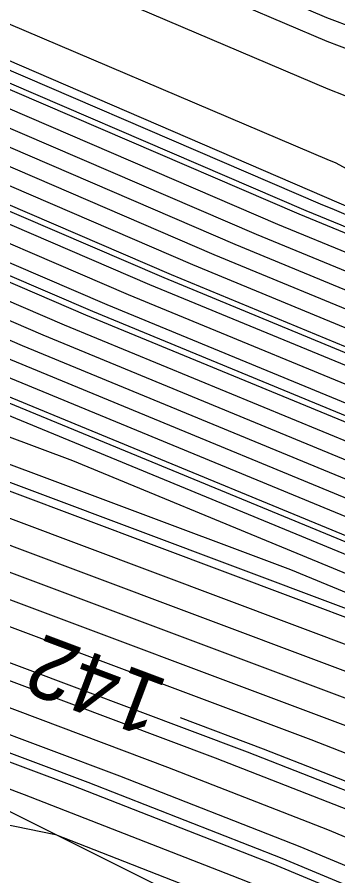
# Model space of a CAD drawing. Extents: x 2354170 to 2357230, y 866100 to 868290.
# Drawn here: x 2355142.84 to 2355153.3, y 867504.12 to 867532.18 of the extents above; entities that cross this region are included whole.
import ezdxf

# ---------------------------------------------------------------- set-up
doc = ezdxf.new("R2010")
doc.units = 0
for name, color, linetype in [('Default', 7, 'Continuous'), ('DTM Contours Major', 7, 'Continuous'), ('DTM Contours Minor', 7, 'Continuous'), ('PH Exist DTM Breakline', 7, 'Continuous')]:
    doc.layers.add(name, color=color, linetype=linetype)

msp = doc.modelspace()

# ---------------------------------------------------------------- linework, layer by layer
at = {"layer": 'Default'}
for points in [[(2355039.748, 867582.774), (2355057.845, 867572.501), (2355066.09, 867568.423), (2355075.66, 867563.616), (2355088.2, 867558.035), (2355090.288, 867556.998), (2355109.078, 867548.638), (2355117.687, 867544.873), (2355118.143, 867544.673), (2355135.4, 867537.032), (2355142.924, 867534.128), (2355152.971, 867529.837), (2355153.53, 867529.622), (2355160.154, 867526.024), (2355180.934, 867517.127), (2355182.414, 867516.349), (2355190.855, 867512.84), (2355199.936, 867509.264)], [(2355030.605, 867581.098), (2355048.031, 867569.375), (2355053.29, 867566.596), (2355066.627, 867561.622), (2355069.054, 867560.678), (2355086.4, 867553.004), (2355087.112, 867552.723), (2355112.383, 867541.543), (2355114.567, 867540.679), (2355114.963, 867540.522), (2355137.014, 867531.279), (2355139.122, 867530.678), (2355151.331, 867525.417), (2355153.823, 867524.387), (2355178.286, 867513.844), (2355180.51, 867512.86), (2355190.971, 867508.066), (2355192.601, 867507.384), (2355218.305, 867495.571)], [(2354995.047, 867580.65), (2355018.365, 867571.741), (2355022.674, 867569.867), (2355022.938, 867569.764), (2355041.304, 867560.814), (2355048.738, 867556.887), (2355052.264, 867555.571), (2355072.009, 867547.892), (2355078.691, 867544.936), (2355084.387, 867542.691), (2355094.899, 867538.04), (2355111.939, 867531.298), (2355115.029, 867530.075), (2355125.868, 867525.532), (2355139.851, 867521.546), (2355141.602, 867520.791), (2355158.318, 867513.884), (2355164.901, 867511.046), (2355180.153, 867504.304), (2355183.645, 867502.704), (2355196.955, 867497.127)], [(2355029.69, 867579.758), (2355040.479, 867572.499), (2355052.965, 867565.903), (2355065.601, 867561.19), (2355069.265, 867559.765), (2355085.849, 867552.427), (2355086.917, 867552.006), (2355111.135, 867541.292), (2355114.379, 867540.009), (2355114.968, 867539.776), (2355136.218, 867530.869), (2355139.174, 867530.026), (2355150.636, 867525.087), (2355154.144, 867523.637), (2355177.33, 867513.644), (2355180.485, 867512.249), (2355190.448, 867507.683), (2355192.912, 867506.651), (2355217.532, 867495.337)], [(2355043.958, 867577.984), (2355056.525, 867570.85), (2355067.342, 867565.501), (2355072.214, 867563.054), (2355087.851, 867556.095), (2355088.894, 867555.577), (2355112.103, 867545.25), (2355116.28, 867543.423), (2355116.501, 867543.327), (2355137.772, 867533.908), (2355140.329, 867532.921), (2355153.012, 867527.504), (2355153.21, 867527.428), (2355155.552, 867526.156), (2355180.709, 867515.384), (2355181.269, 867515.089), (2355191.411, 867510.874), (2355196.056, 867509.044)], [(2355028.633, 867577.026), (2355052.315, 867564.516), (2355063.549, 867560.326), (2355069.688, 867557.938), (2355084.748, 867551.275), (2355086.528, 867550.573), (2355108.637, 867540.792), (2355114.004, 867538.669), (2355114.977, 867538.283), (2355134.626, 867530.048), (2355139.278, 867528.721), (2355149.246, 867524.426), (2355154.786, 867522.137), (2355175.418, 867513.244), (2355180.434, 867511.027), (2355189.401, 867506.917), (2355193.534, 867505.186)], [(2355002.655, 867575.912), (2355019.366, 867569.527), (2355021.702, 867568.511), (2355022.012, 867568.39), (2355043.608, 867557.866), (2355048.087, 867555.5), (2355050.212, 867554.707), (2355072.431, 867546.066), (2355077.59, 867543.784), (2355083.997, 867541.258), (2355092.402, 867537.54), (2355111.563, 867529.958), (2355115.038, 867528.583), (2355124.276, 867524.711), (2355139.955, 867520.242), (2355140.213, 867520.131), (2355158.96, 867512.383), (2355162.989, 867510.647), (2355180.102, 867503.082), (2355182.598, 867501.938), (2355197.577, 867495.662)], [(2355029.785, 867575.552), (2355051.989, 867563.822), (2355062.523, 867559.893), (2355069.899, 867557.025), (2355084.197, 867550.699), (2355086.333, 867549.857), (2355107.388, 867540.542), (2355113.816, 867537.999), (2355114.982, 867537.537), (2355133.83, 867529.637), (2355139.331, 867528.069), (2355148.551, 867524.095), (2355155.107, 867521.386), (2355174.462, 867513.045), (2355180.408, 867510.416), (2355188.878, 867506.534), (2355193.845, 867504.453)], [(2355196.022, 867499.325), (2355185.215, 867503.853), (2355180.229, 867506.138), (2355167.77, 867511.646), (2355157.355, 867516.135), (2355143.687, 867521.783), (2355139.695, 867523.503), (2355128.257, 867526.764), (2355115.015, 867532.314), (2355112.502, 867533.308), (2355098.646, 867538.791), (2355084.971, 867544.841), (2355080.343, 867546.665), (2355071.376, 867550.632), (2355055.342, 867556.868), (2355049.713, 867558.967), (2355037.849, 867565.235), (2355024.326, 867571.825), (2355024.132, 867571.901), (2355016.865, 867575.061)], [(2355194.778, 867502.255), (2355187.308, 867505.385), (2355180.331, 867508.582), (2355171.594, 867512.445), (2355156.07, 867519.136), (2355146.466, 867523.104), (2355139.487, 867526.112), (2355131.441, 867528.406), (2355114.996, 867535.299), (2355113.253, 867535.988), (2355103.641, 867539.791), (2355085.749, 867547.707), (2355082.545, 867548.97), (2355070.532, 867554.285), (2355059.445, 867558.597), (2355051.014, 867561.741), (2355033.241, 867571.131), (2355026.177, 867574.573)], [(2354998.866, 867573.748), (2355010.208, 867572.11), (2355019.866, 867568.42), (2355021.216, 867567.833), (2355021.55, 867567.703), (2355044.76, 867556.392), (2355047.762, 867554.806), (2355049.186, 867554.275), (2355072.643, 867545.153), (2355077.039, 867543.207), (2355083.803, 867540.541), (2355091.153, 867537.289), (2355111.376, 867529.288), (2355115.043, 867527.837), (2355123.48, 867524.301), (2355138.516, 867520.014), (2355140.061, 867519.404), (2355144.636, 867517.685), (2355159.281, 867511.633), (2355162.033, 867510.447), (2355180.076, 867502.471), (2355182.075, 867501.555), (2355197.888, 867494.929)], [(2355195.089, 867501.523), (2355186.785, 867505.002), (2355180.306, 867507.971), (2355170.638, 867512.245), (2355156.392, 867518.385), (2355145.772, 867522.774), (2355139.539, 867525.46), (2355130.645, 867527.995), (2355115.001, 867534.553), (2355113.065, 867535.318), (2355102.393, 867539.541), (2355085.555, 867546.99), (2355081.995, 867548.394), (2355070.743, 867553.372), (2355058.419, 867558.165), (2355050.689, 867561.048), (2355034.393, 867569.657), (2355025.715, 867573.886)], [(2355048.169, 867573.195), (2355055.206, 867569.2), (2355068.594, 867562.579), (2355068.769, 867562.491), (2355086.8, 867554.466), (2355087.501, 867554.156), (2355087.501, 867554.156), (2355114.881, 867542.043), (2355114.942, 867542.019), (2355114.954, 867542.014), (2355138.607, 867532.1), (2355139.018, 867531.983), (2355152.72, 867526.078), (2355153.181, 867525.888), (2355180.198, 867514.243), (2355180.561, 867514.083), (2355190.76, 867509.409), (2355191.967, 867508.907), (2355192.176, 867508.825), (2355218.458, 867497.985)], [(2355017.865, 867572.848), (2355023.16, 867570.545), (2355023.401, 867570.451), (2355040.152, 867562.287), (2355049.063, 867557.58), (2355053.29, 867556.004), (2355071.798, 867548.806), (2355079.242, 867545.512), (2355084.581, 867543.407), (2355096.148, 867538.29), (2355112.126, 867531.968), (2355115.024, 867530.822), (2355126.665, 867525.943), (2355139.799, 867522.198), (2355142.297, 867521.122), (2355157.997, 867514.634), (2355165.857, 867511.246), (2355180.178, 867504.915), (2355184.168, 867503.087), (2355196.644, 867497.86)], [(2355195.711, 867500.057), (2355185.738, 867504.236), (2355180.255, 867506.749), (2355168.726, 867511.846), (2355157.034, 867516.885), (2355144.382, 867522.113), (2355139.643, 867524.155), (2355129.053, 867527.174), (2355115.01, 867533.06), (2355112.69, 867533.978), (2355099.895, 867539.041), (2355085.165, 867545.557), (2355080.893, 867547.241), (2355071.165, 867551.545), (2355056.368, 867557.3), (2355050.038, 867559.661), (2355036.697, 867566.709), (2355024.789, 867572.512), (2355024.618, 867572.579)], [(2355194.467, 867502.988), (2355187.831, 867505.768), (2355180.357, 867509.194), (2355172.55, 867512.645), (2355155.749, 867519.886), (2355147.161, 867523.435), (2355139.435, 867526.765), (2355132.238, 867528.816), (2355114.991, 867536.045), (2355113.441, 867536.658), (2355104.89, 867540.042), (2355085.944, 867548.423), (2355083.096, 867549.546), (2355070.321, 867555.198), (2355060.471, 867559.029), (2355051.339, 867562.435), (2355032.089, 867572.605)], [(2355001.207, 867570.699), (2355017.762, 867568.308), (2355020.366, 867567.313), (2355020.73, 867567.155), (2355021.087, 867567.016), (2355045.912, 867554.918), (2355047.437, 867554.112), (2355048.16, 867553.843), (2355072.854, 867544.239), (2355076.489, 867542.631), (2355083.608, 867539.825), (2355089.904, 867537.039), (2355111.188, 867528.618), (2355115.048, 867527.091), (2355122.684, 867523.89), (2355136.293, 867520.011), (2355140.195, 867518.469), (2355151.754, 867514.126), (2355159.602, 867510.883), (2355161.077, 867510.247), (2355180.05, 867501.86), (2355181.552, 867501.172), (2355198.199, 867494.196)], [(2355070.126, 867550.287), (2355071.587, 867549.719), (2355079.792, 867546.089), (2355084.776, 867544.124), (2355097.397, 867538.54), (2355112.314, 867532.638), (2355115.02, 867531.568), (2355127.461, 867526.353), (2355139.747, 867522.851), (2355142.992, 867521.452), (2355157.676, 867515.384), (2355162.877, 867513.143)], [(2355177.5, 867508.589), (2355169.682, 867512.045), (2355156.713, 867517.635), (2355145.077, 867522.443), (2355139.591, 867524.808), (2355129.849, 867527.585), (2355115.005, 867533.806), (2355112.877, 867534.648), (2355101.144, 867539.291), (2355085.36, 867546.274), (2355085.011, 867546.411)], [(2355074.048, 867546.171), (2355078.14, 867544.36), (2355084.192, 867541.974), (2355093.651, 867537.79), (2355111.751, 867530.628), (2355115.034, 867529.329), (2355125.072, 867525.122), (2355139.903, 867520.894), (2355140.907, 867520.461), (2355158.639, 867513.134), (2355163.945, 867510.847), (2355166.979, 867509.506)], [(2355099.408, 867545.678), (2355109.886, 867541.042), (2355114.192, 867539.339), (2355114.972, 867539.03), (2355135.422, 867530.458), (2355139.226, 867529.374), (2355149.941, 867524.756), (2355154.465, 867522.887), (2355176.374, 867513.444), (2355180.459, 867511.638), (2355189.925, 867507.3), (2355191.442, 867506.665)], [(2355095.736, 867544.894), (2355106.139, 867540.292), (2355113.628, 867537.328), (2355114.987, 867536.791), (2355133.034, 867529.227), (2355139.383, 867527.417), (2355147.856, 867523.765), (2355155.428, 867520.636), (2355173.506, 867512.845), (2355180.383, 867509.805), (2355187.942, 867506.34)], [(2355075.387, 867541.479), (2355083.219, 867538.391), (2355087.406, 867536.539), (2355110.812, 867527.278), (2355115.057, 867525.598), (2355121.092, 867523.069), (2355131.846, 867520.003), (2355140.464, 867516.599), (2355158.655, 867509.764), (2355159.218, 867509.544), (2355160.871, 867508.852), (2355169.056, 867505.475), (2355179.999, 867500.637), (2355180.505, 867500.406), (2355198.821, 867492.731)], [(2355199.132, 867491.999), (2355179.982, 867500.023), (2355179.974, 867500.026), (2355179.803, 867500.102), (2355161.933, 867507.475), (2355158.324, 867508.984), (2355157.096, 867509.466), (2355140.598, 867515.664), (2355129.622, 867520), (2355120.295, 867522.659), (2355115.062, 867524.852), (2355110.625, 867526.608), (2355086.157, 867536.289), (2355083.024, 867537.675), (2355074.837, 867540.902)], [(2355075.489, 867539.058), (2355082.635, 867536.242), (2355083.66, 867535.788), (2355110.249, 867525.268), (2355115.071, 867523.36), (2355118.703, 867521.838), (2355125.176, 867519.992), (2355140.867, 867513.794), (2355153.977, 867508.868), (2355156.537, 867507.865), (2355164.057, 867504.72), (2355179.317, 867498.424), (2355181.309, 867497.592), (2355194.726, 867492.64)], [(2355085.248, 867538.296), (2355088.655, 867536.789), (2355111, 867527.948), (2355115.053, 867526.344), (2355121.888, 867523.48), (2355134.069, 867520.007), (2355140.33, 867517.534), (2355158.871, 867510.568), (2355159.923, 867510.133), (2355160.121, 867510.047), (2355178.336, 867501.995)], [(2355075.248, 867536.875), (2355082.374, 867535.497), (2355082.449, 867535.477), (2355082.497, 867535.467), (2355082.53, 867535.459), (2355082.7, 867535.424), (2355110.061, 867524.598), (2355115.076, 867522.614), (2355117.907, 867521.427), (2355122.952, 867519.989), (2355141.002, 867512.859), (2355152.417, 867508.57), (2355155.644, 867507.306), (2355165.119, 867503.342), (2355178.986, 867497.621), (2355181.982, 867496.37), (2355199.705, 867489.829)], [(2355143.722, 867536.028), (2355145.519, 867535.335), (2355152.929, 867532.17), (2355153.849, 867531.817), (2355164.756, 867525.893), (2355181.159, 867518.869), (2355183.559, 867517.609), (2355190.3, 867514.807), (2355203.816, 867509.484), (2355216.916, 867504.081), (2355224.347, 867501.177), (2355226.666, 867500.212), (2355235.349, 867496.169)], [(2355131.737, 867534.235), (2355137.811, 867531.69), (2355139.07, 867531.331), (2355152.025, 867525.748), (2355153.502, 867525.137), (2355179.242, 867514.044), (2355180.536, 867513.472), (2355191.495, 867508.449), (2355192.29, 867508.116), (2355216.867, 867496.821), (2355218.972, 867495.953), (2355219.122, 867495.895), (2355223.326, 867494.145)], [(2355078.244, 867531.76), (2355082.735, 867530.572), (2355086.184, 867529.868), (2355088.6, 867529.248), (2355101.028, 867526.683), (2355109.686, 867523.258), (2355115.086, 867521.121), (2355116.315, 867520.606), (2355118.505, 867519.982), (2355141.27, 867510.989), (2355149.298, 867507.972), (2355153.857, 867506.187), (2355167.243, 867500.587), (2355178.323, 867496.015), (2355183.329, 867493.925), (2355197.882, 867488.554)], [(2355078.525, 867524.816), (2355080.751, 867525.891), (2355081.125, 867526.093), (2355081.222, 867526.162), (2355082.532, 867527.165), (2355082.836, 867527.223), (2355083.654, 867527.418), (2355084.337, 867527.28), (2355087.516, 867527.173), (2355088.028, 867527.069), (2355091.635, 867526.143), (2355107.832, 867522.8), (2355108.933, 867522.576), (2355109.311, 867522.491), (2355109.516, 867522.455), (2355110.192, 867522.313), (2355115.09, 867520.375), (2355115.519, 867520.196), (2355116.282, 867519.978), (2355141.405, 867510.054), (2355147.739, 867507.674), (2355152.963, 867505.627), (2355168.305, 867499.21)], [(2355199.755, 867491.123), (2355199.443, 867491.266), (2355187.291, 867496.358), (2355180.636, 867498.814), (2355179.648, 867499.226), (2355162.995, 867506.097), (2355157.431, 867508.425), (2355155.536, 867509.167), (2355140.733, 867514.729), (2355127.399, 867519.996), (2355119.499, 867522.248), (2355115.067, 867524.106), (2355110.437, 867525.938), (2355106.638, 867527.441)], [(2355169.367, 867497.832), (2355152.07, 867505.068), (2355146.179, 867507.375), (2355141.539, 867509.119), (2355118.986, 867518.028), (2355116.412, 867518.506), (2355115.866, 867518.637), (2355115.082, 867518.839), (2355113.848, 867519.102), (2355109.574, 867520.001), (2355106.607, 867520.524), (2355101.129, 867521.749)], [(2355119.972, 867515.213), (2355127.354, 867513.84), (2355141.674, 867508.184), (2355144.62, 867507.077), (2355151.176, 867504.508), (2355170.429, 867496.455), (2355177.33, 867493.607), (2355185.348, 867490.259), (2355195.147, 867486.643), (2355205.884, 867482.442), (2355213.315, 867479.737)], [(2355105.876, 867511.479), (2355106.974, 867511.989), (2355107.622, 867512.473), (2355108.844, 867513.303), (2355109.161, 867513.54), (2355109.254, 867513.616), (2355109.412, 867513.788), (2355109.736, 867513.836), (2355112.284, 867514.468), (2355113.396, 867514.299), (2355115.036, 867513.949), (2355119.189, 867512.88), (2355122.081, 867512.189), (2355135.722, 867509.653), (2355141.808, 867507.248), (2355143.06, 867506.778), (2355150.283, 867503.949), (2355171.491, 867495.077)], [(2355122.973, 867509.494), (2355124.916, 867509.03), (2355134.341, 867507.278), (2355139.899, 867506.341), (2355141.191, 867506.048), (2355141.899, 867505.916), (2355144.09, 867505.465), (2355149.389, 867503.389), (2355172.553, 867493.7)], [(2355148.153, 867509.287), (2355150.858, 867508.271), (2355154.75, 867506.746), (2355166.181, 867501.965), (2355178.654, 867496.818), (2355182.655, 867495.147), (2355198.794, 867489.192), (2355201.418, 867488.165), (2355209.722, 867485.142), (2355219.926, 867480.803), (2355220.228, 867480.676), (2355221.755, 867480.016), (2355225.573, 867476.529), (2355235.92, 867474.071), (2355240.516, 867472.183)]]:
    msp.add_lwpolyline(points, dxfattribs=at)
at = {"layer": 'DTM Contours Major'}
for points in [[(2355063.712, 867547.241), (2355072.994, 867543.631), (2355076.122, 867542.247), (2355083.478, 867539.347), (2355089.071, 867536.872), (2355111.063, 867528.171), (2355115.051, 867526.593), (2355122.153, 867523.616), (2355134.81, 867520.008), (2355140.285, 867517.846), (2355156.499, 867511.754), (2355157.043, 867511.529)], [(2355099.408, 867545.678), (2355109.886, 867541.042), (2355114.192, 867539.339), (2355114.972, 867539.03), (2355135.422, 867530.458), (2355139.226, 867529.374), (2355149.941, 867524.756), (2355154.465, 867522.887), (2355176.374, 867513.444), (2355180.459, 867511.638), (2355189.925, 867507.3), (2355191.442, 867506.665)]]:
    msp.add_lwpolyline(points, dxfattribs=at)
at = {"layer": 'DTM Contours Minor'}
for points in [[(2354998.582, 867581.131), (2355017.365, 867573.955), (2355023.646, 867571.223), (2355023.864, 867571.138), (2355039.001, 867563.761), (2355049.388, 867558.274), (2355054.316, 867556.436), (2355071.587, 867549.719), (2355079.792, 867546.089), (2355084.776, 867544.124), (2355097.397, 867538.54), (2355112.314, 867532.638), (2355115.02, 867531.568), (2355127.461, 867526.353), (2355139.747, 867522.851), (2355142.992, 867521.452), (2355157.676, 867515.384), (2355166.814, 867511.446), (2355180.204, 867505.527), (2355182.997, 867504.246)], [(2355025.557, 867567.271), (2355042.84, 867558.848), (2355048.304, 867555.962), (2355050.896, 867554.995), (2355072.291, 867546.675), (2355077.957, 867544.168), (2355084.127, 867541.735), (2355093.234, 867537.706), (2355111.688, 867530.405), (2355115.035, 867529.081), (2355124.807, 867524.985), (2355139.92, 867520.676), (2355140.676, 867520.351), (2355158.746, 867512.884), (2355163.627, 867510.78), (2355180.119, 867503.489), (2355182.947, 867502.193), (2355197.37, 867496.15), (2355206.448, 867491.978), (2355210.008, 867490.464)], [(2355115.591, 867547.166), (2355118.626, 867545.839), (2355119.238, 867545.571), (2355133.819, 867539.115), (2355144.654, 867534.933), (2355152.943, 867531.392), (2355153.743, 867531.085), (2355163.222, 867525.936), (2355181.084, 867518.288), (2355183.177, 867517.189), (2355190.485, 867514.152), (2355202.522, 867509.411), (2355217.087, 867503.404), (2355223.911, 867500.737), (2355226.535, 867499.645), (2355241.683, 867492.593), (2355253.966, 867487.474), (2355260.351, 867484.508), (2355267.475, 867481.396), (2355284.39, 867476.569), (2355295.537, 867471.814), (2355300.054, 867470.541)], [(2355111.207, 867543.133), (2355114.049, 867541.876), (2355114.817, 867541.572), (2355114.957, 867541.517), (2355138.076, 867531.827), (2355139.053, 867531.548), (2355152.257, 867525.858), (2355153.395, 867525.388), (2355179.561, 867514.11), (2355180.544, 867513.675), (2355191.669, 867508.577), (2355192.186, 867508.36), (2355208.165, 867501.017), (2355218.801, 867496.63), (2355219.558, 867496.335), (2355225.225, 867493.976), (2355226.966, 867493.166), (2355252.869, 867482.371), (2355253.717, 867481.977), (2355268.595, 867475.479), (2355271.849, 867474.55), (2355295.1, 867464.632)], [(2355314.763, 867453.12), (2355298.575, 867457.547), (2355294.777, 867459.009), (2355293.478, 867459.583), (2355289.988, 867461.088), (2355269.138, 867470.58), (2355267.185, 867471.418), (2355263.706, 867472.963), (2355251.931, 867478.321), (2355250.098, 867479.223), (2355245.542, 867481.094), (2355226.618, 867489.039), (2355223.893, 867490.216), (2355219.235, 867492.172), (2355214.181, 867494.321), (2355194.259, 867503.476), (2355188.18, 867506.023), (2355180.374, 867509.601), (2355173.187, 867512.778), (2355155.535, 867520.386), (2355147.625, 867523.655), (2355139.4, 867527.199), (2355132.768, 867529.09), (2355130.416, 867530.076)], [(2355313.363, 867451.539), (2355300.128, 867455.159), (2355293.984, 867457.525), (2355291.882, 867458.452), (2355286.236, 867460.887), (2355269.295, 867468.6), (2355266.233, 867469.913), (2355260.78, 867472.335), (2355251.514, 867476.552), (2355248.689, 867477.942), (2355241.666, 867480.826), (2355227.454, 867486.792), (2355223.272, 867488.599), (2355219.352, 867490.245), (2355211.603, 867493.54), (2355195.296, 867501.034), (2355186.436, 867504.747), (2355180.289, 867507.564), (2355170, 867512.112), (2355156.606, 867517.885), (2355145.308, 867522.554), (2355139.573, 867525.025), (2355130.114, 867527.721), (2355128.897, 867528.232)], [(2355109.625, 867523.778), (2355109.811, 867523.704), (2355115.082, 867521.619), (2355116.845, 867520.88), (2355119.987, 867519.984), (2355141.181, 867511.612), (2355150.338, 867508.172), (2355154.453, 867506.56), (2355166.535, 867501.506), (2355178.544, 867496.551), (2355182.88, 867494.74), (2355198.49, 867488.979)], [(2355199.443, 867491.266), (2355187.291, 867496.358), (2355180.636, 867498.814), (2355179.648, 867499.226), (2355162.995, 867506.097), (2355157.431, 867508.425), (2355155.536, 867509.167), (2355140.733, 867514.729), (2355127.399, 867519.996), (2355123.47, 867521.116)], [(2355104.805, 867519.213), (2355109.613, 867518.365), (2355112.064, 867517.849), (2355115.067, 867517.209), (2355116.973, 867516.718), (2355118.302, 867516.401), (2355124.565, 867515.236), (2355141.629, 867508.495), (2355145.139, 867507.176), (2355151.474, 867504.695), (2355170.075, 867496.914)]]:
    msp.add_lwpolyline(points, dxfattribs=at)
at = {"layer": 'PH Exist DTM Breakline'}
for points in [[(2355219.015, 867495.786), (2355180.571, 867514.321), (2355138.993, 867532.299), (2355114.953, 867542.057), (2355068.64, 867562.47), (2355053.527, 867567.101), (2355028.202, 867577.578)], [(2355020.895, 867566.731), (2355047.101, 867553.397), (2355082.445, 867535.545), (2355115.093, 867519.976), (2355148.878, 867503.069), (2355189.51, 867482.704), (2355236.497, 867458.891), (2355265.87, 867444.934), (2355289.255, 867433.719), (2355311.059, 867425.353), (2355318.523, 867424.7), (2355331.045, 867424.483), (2355346.844, 867422.718), (2355351.323, 867421.656), (2355352.941, 867418.753), (2355356.257, 867418.279), (2355358.394, 867419.067), (2355358.413, 867422.341), (2355356.281, 867425.567), (2355354.45, 867428.091), (2355352.258, 867431.151), (2355351.487, 867427.072), (2355351.536, 867425.452)]]:
    msp.add_lwpolyline(points, dxfattribs=at)

# ---------------------------------------------------------------- texts
at = {"layer": 'Default'}
msp.add_text('142', height=2, rotation=159.4078, dxfattribs=at).set_placement((2355147.827, 867510.478))

doc.saveas('drawing.dxf')
